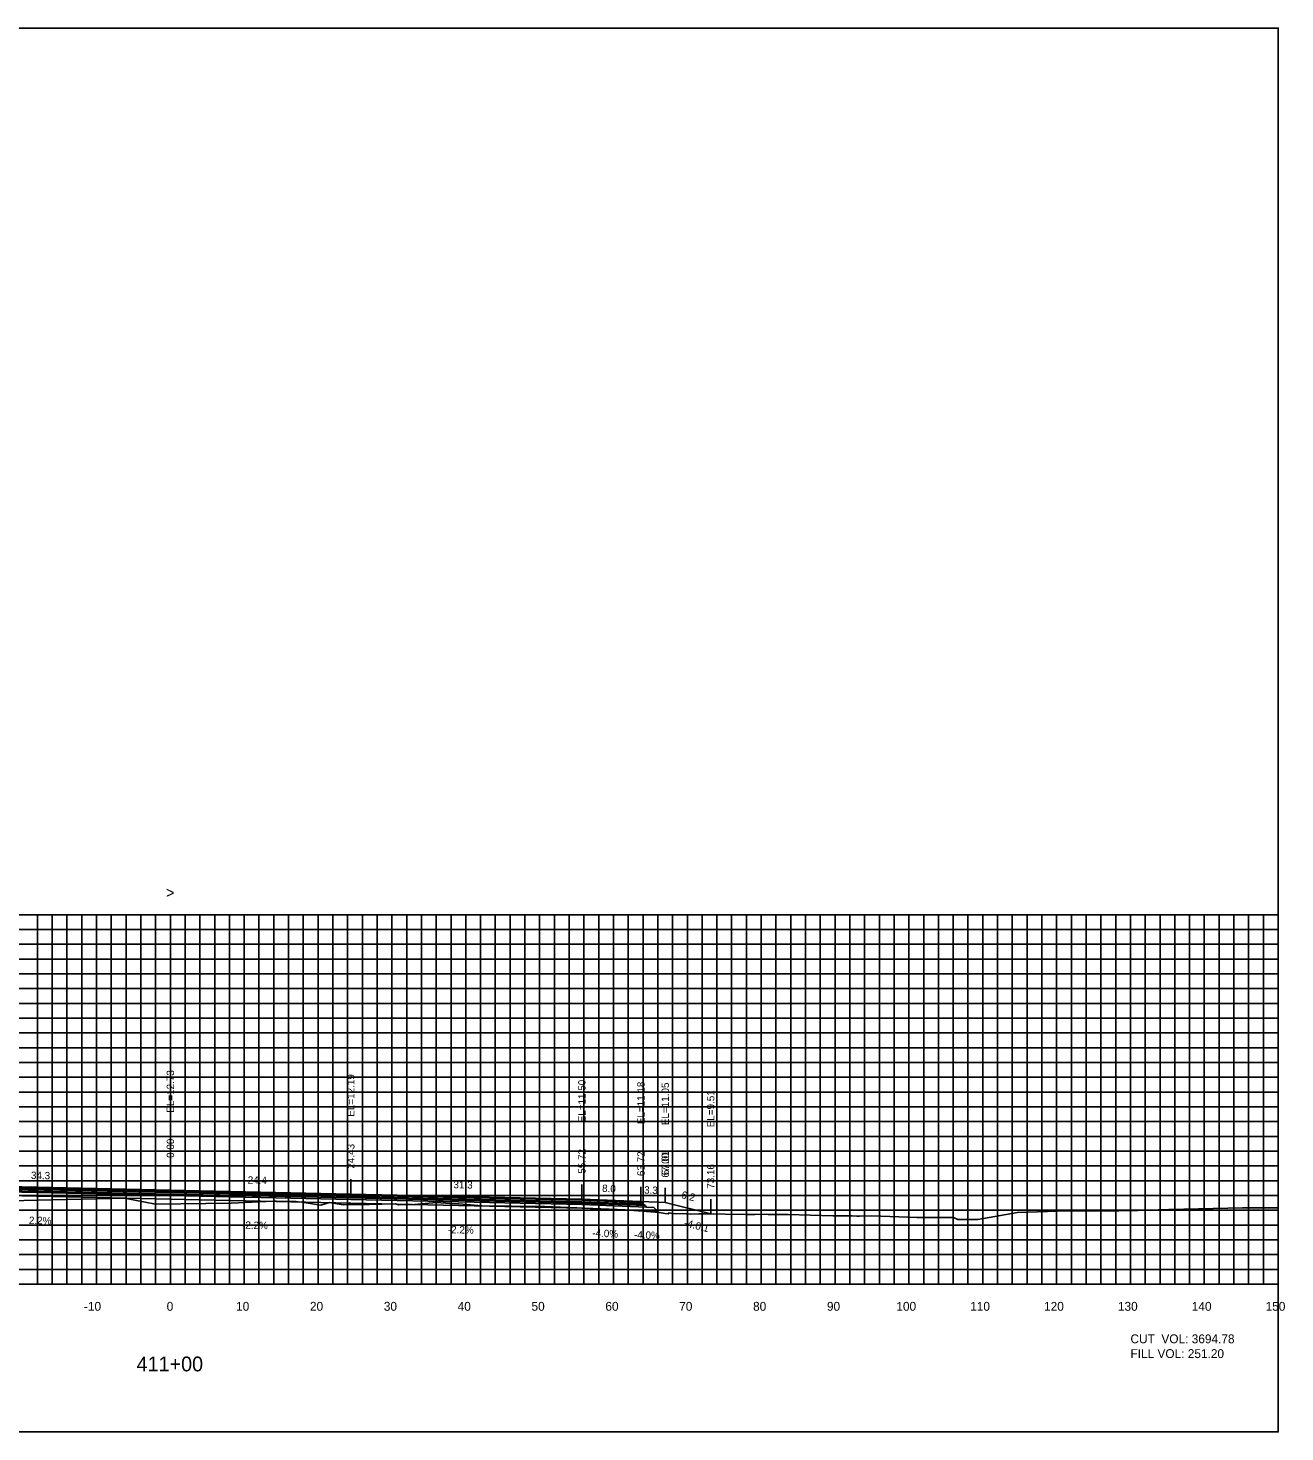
# Model space of a CAD drawing. Extents: x 1800976 to 1805104, y 250057 to 250580.
# Drawn here: x 1804651.7 to 1804821.9, y 250079.4 to 250269.4 of the extents above; entities that cross this region are included whole.
import ezdxf

# ---------------------------------------------------------------- set-up
doc = ezdxf.new("R2010")
doc.units = 0
for name, color, linetype in [('1', 7, 'Continuous'), ('10', 7, 'Continuous'), ('3', 7, 'Continuous'), ('4', 7, 'Continuous'), ('60', 7, 'Continuous'), ('ANNO-TXT', 7, 'Continuous'), ('BASE', 7, 'Continuous'), ('CL-CNST', 7, 'Continuous'), ('Level 62', 7, 'Continuous'), ('LOWER BINDER', 7, 'Continuous'), ('M-ROADS', 7, 'Continuous'), ('UPPER BINDER', 7, 'Continuous'), ('WEARING', 7, 'Continuous')]:
    doc.layers.add(name, color=color, linetype=linetype)

msp = doc.modelspace()

# ---------------------------------------------------------------- linework, layer by layer
for p, q in [((1804671, 250112.16), (1804671, 250114.16)), ((1804695.43, 250111.62), (1804695.43, 250113.62)), ((1804695.43, 250111.62), (1804695.43, 250113.62)), ((1804726.72, 250110.93), (1804726.72, 250112.93)), ((1804734.72, 250110.61), (1804734.72, 250112.61)), ((1804738.01, 250110.48), (1804738.01, 250112.48)), ((1804738.01, 250110.48), (1804738.01, 250112.48)), ((1804744.16, 250108.94), (1804744.16, 250110.94))]:
    msp.add_line(p, q)
msp.add_lwpolyline([(1804521, 250079.43), (1804821, 250079.43), (1804821, 250269.43), (1804521, 250269.43)], close=True)
at = {"layer": '60'}
for p, q in [((1804821, 250099.43), (1804821, 250149.43)), ((1804821.06, 250149.43), (1804821, 250149.43)), ((1804821.06, 250139.43), (1804821, 250139.43)), ((1804821.06, 250129.43), (1804821, 250129.43)), ((1804821.06, 250119.43), (1804821, 250119.43)), ((1804821.06, 250109.43), (1804821, 250109.43)), ((1804521, 250099.43), (1804821, 250099.43)), ((1804661, 250099.37), (1804661, 250099.43)), ((1804671, 250099.37), (1804671, 250099.43)), ((1804681, 250099.37), (1804681, 250099.43)), ((1804691, 250099.37), (1804691, 250099.43)), ((1804701, 250099.37), (1804701, 250099.43)), ((1804711, 250099.37), (1804711, 250099.43)), ((1804721, 250099.37), (1804721, 250099.43)), ((1804731, 250099.37), (1804731, 250099.43)), ((1804741, 250099.37), (1804741, 250099.43)), ((1804751, 250099.37), (1804751, 250099.43)), ((1804761, 250099.37), (1804761, 250099.43)), ((1804771, 250099.37), (1804771, 250099.43)), ((1804781, 250099.37), (1804781, 250099.43)), ((1804791, 250099.37), (1804791, 250099.43)), ((1804801, 250099.37), (1804801, 250099.43)), ((1804811, 250099.37), (1804811, 250099.43)), ((1804821, 250099.37), (1804821, 250099.43)), ((1804821.06, 250099.43), (1804821, 250099.43))]:
    msp.add_line(p, q, dxfattribs=at)
at = {"layer": 'BASE'}
msp.add_lwpolyline([(1804584.14, 250112.99), (1804585.14, 250113.03), (1804589.89, 250113.22), (1804636.73, 250112.2), (1804671, 250111.44), (1804695.43, 250110.91), (1804726.72, 250110.21), (1804735.47, 250109.86), (1804736.47, 250109.82), (1804736.99, 250109.3), (1804726.72, 250109.71), (1804695.43, 250110.41), (1804671, 250110.94), (1804636.73, 250111.7), (1804589.89, 250112.72), (1804583.62, 250112.47)], close=True, dxfattribs=at)
at = {"layer": 'CL-CNST'}
msp.add_lwpolyline([(1804554.98, 250110.17), (1804555.39, 250110.06), (1804559.39, 250110.06), (1804580.39, 250113.56), (1804585.89, 250113.78), (1804589.89, 250113.94), (1804636.72, 250112.91), (1804671, 250112.16), (1804695.43, 250111.62), (1804695.43, 250111.62), (1804726.72, 250110.93), (1804734.72, 250110.61), (1804738.01, 250110.48), (1804738.01, 250110.48), (1804744.16, 250108.94)], dxfattribs=at)
at = {"layer": 'Level 62'}
for p, q in [((1804521, 250149.43), (1804821, 250149.43)), ((1804653, 250099.43), (1804653, 250149.43)), ((1804655, 250099.43), (1804655, 250149.43)), ((1804657, 250099.43), (1804657, 250149.43)), ((1804659, 250099.43), (1804659, 250149.43)), ((1804661, 250099.43), (1804661, 250149.43)), ((1804663, 250099.43), (1804663, 250149.43)), ((1804665, 250099.43), (1804665, 250149.43)), ((1804667, 250099.43), (1804667, 250149.43)), ((1804669, 250099.43), (1804669, 250149.43)), ((1804671, 250099.43), (1804671, 250149.43)), ((1804673, 250099.43), (1804673, 250149.43)), ((1804675, 250099.43), (1804675, 250149.43)), ((1804677, 250099.43), (1804677, 250149.43)), ((1804679, 250099.43), (1804679, 250149.43)), ((1804681, 250099.43), (1804681, 250149.43)), ((1804683, 250099.43), (1804683, 250149.43)), ((1804685, 250099.43), (1804685, 250149.43)), ((1804687, 250099.43), (1804687, 250149.43)), ((1804689, 250099.43), (1804689, 250149.43)), ((1804691, 250099.43), (1804691, 250149.43)), ((1804693, 250099.43), (1804693, 250149.43)), ((1804695, 250099.43), (1804695, 250149.43)), ((1804697, 250099.43), (1804697, 250149.43)), ((1804699, 250099.43), (1804699, 250149.43)), ((1804701, 250099.43), (1804701, 250149.43)), ((1804703, 250099.43), (1804703, 250149.43)), ((1804705, 250099.43), (1804705, 250149.43)), ((1804707, 250099.43), (1804707, 250149.43)), ((1804709, 250099.43), (1804709, 250149.43)), ((1804711, 250099.43), (1804711, 250149.43)), ((1804713, 250099.43), (1804713, 250149.43)), ((1804715, 250099.43), (1804715, 250149.43)), ((1804717, 250099.43), (1804717, 250149.43)), ((1804719, 250099.43), (1804719, 250149.43)), ((1804721, 250099.43), (1804721, 250149.43)), ((1804723, 250099.43), (1804723, 250149.43)), ((1804725, 250099.43), (1804725, 250149.43)), ((1804727, 250099.43), (1804727, 250149.43)), ((1804729, 250099.43), (1804729, 250149.43)), ((1804731, 250099.43), (1804731, 250149.43)), ((1804733, 250099.43), (1804733, 250149.43)), ((1804735, 250099.43), (1804735, 250149.43)), ((1804737, 250099.43), (1804737, 250149.43)), ((1804739, 250099.43), (1804739, 250149.43)), ((1804741, 250099.43), (1804741, 250149.43)), ((1804743, 250099.43), (1804743, 250149.43)), ((1804745, 250099.43), (1804745, 250149.43)), ((1804747, 250099.43), (1804747, 250149.43)), ((1804749, 250099.43), (1804749, 250149.43)), ((1804751, 250099.43), (1804751, 250149.43)), ((1804753, 250099.43), (1804753, 250149.43)), ((1804755, 250099.43), (1804755, 250149.43)), ((1804757, 250099.43), (1804757, 250149.43)), ((1804759, 250099.43), (1804759, 250149.43)), ((1804761, 250099.43), (1804761, 250149.43)), ((1804763, 250099.43), (1804763, 250149.43)), ((1804765, 250099.43), (1804765, 250149.43)), ((1804767, 250099.43), (1804767, 250149.43)), ((1804769, 250099.43), (1804769, 250149.43)), ((1804771, 250099.43), (1804771, 250149.43)), ((1804773, 250099.43), (1804773, 250149.43)), ((1804775, 250099.43), (1804775, 250149.43)), ((1804777, 250099.43), (1804777, 250149.43)), ((1804779, 250099.43), (1804779, 250149.43)), ((1804781, 250099.43), (1804781, 250149.43)), ((1804783, 250099.43), (1804783, 250149.43)), ((1804785, 250099.43), (1804785, 250149.43)), ((1804787, 250099.43), (1804787, 250149.43)), ((1804789, 250099.43), (1804789, 250149.43)), ((1804791, 250099.43), (1804791, 250149.43)), ((1804793, 250099.43), (1804793, 250149.43)), ((1804795, 250099.43), (1804795, 250149.43)), ((1804797, 250099.43), (1804797, 250149.43)), ((1804799, 250099.43), (1804799, 250149.43)), ((1804801, 250099.43), (1804801, 250149.43)), ((1804803, 250099.43), (1804803, 250149.43)), ((1804805, 250099.43), (1804805, 250149.43)), ((1804807, 250099.43), (1804807, 250149.43)), ((1804809, 250099.43), (1804809, 250149.43)), ((1804811, 250099.43), (1804811, 250149.43)), ((1804813, 250099.43), (1804813, 250149.43)), ((1804815, 250099.43), (1804815, 250149.43)), ((1804817, 250099.43), (1804817, 250149.43)), ((1804819, 250099.43), (1804819, 250149.43)), ((1804821, 250099.43), (1804821, 250149.43)), ((1804521, 250147.43), (1804821, 250147.43)), ((1804521, 250145.43), (1804821, 250145.43)), ((1804521, 250143.43), (1804821, 250143.43)), ((1804521, 250141.43), (1804821, 250141.43)), ((1804521, 250139.43), (1804821, 250139.43)), ((1804521, 250137.43), (1804821, 250137.43)), ((1804521, 250135.43), (1804821, 250135.43)), ((1804521, 250133.43), (1804821, 250133.43)), ((1804521, 250131.43), (1804821, 250131.43)), ((1804521, 250129.43), (1804821, 250129.43)), ((1804521, 250127.43), (1804821, 250127.43)), ((1804521, 250125.43), (1804821, 250125.43)), ((1804521, 250123.43), (1804821, 250123.43)), ((1804521, 250121.43), (1804821, 250121.43)), ((1804521, 250119.43), (1804821, 250119.43)), ((1804521, 250117.43), (1804821, 250117.43)), ((1804521, 250115.43), (1804821, 250115.43)), ((1804521, 250113.43), (1804821, 250113.43)), ((1804521, 250111.43), (1804821, 250111.43)), ((1804521, 250109.43), (1804821, 250109.43)), ((1804521, 250107.43), (1804821, 250107.43)), ((1804521, 250105.43), (1804821, 250105.43)), ((1804521, 250103.43), (1804821, 250103.43)), ((1804521, 250101.43), (1804821, 250101.43)), ((1804521, 250099.43), (1804821, 250099.43))]:
    msp.add_line(p, q, dxfattribs=at)
at = {"layer": 'LOWER BINDER'}
for points in [[(1804589.89, 250113.41), (1804636.72, 250112.38), (1804671, 250111.63), (1804695.43, 250111.1), (1804726.72, 250110.4), (1804735.27, 250110.06), (1804735.47, 250109.86), (1804726.72, 250110.21), (1804695.43, 250110.91), (1804671, 250111.44), (1804636.73, 250112.2), (1804589.89, 250113.22), (1804585.14, 250113.03), (1804585.34, 250113.23)], [(1804589.89, 250113.6), (1804636.72, 250112.57), (1804671, 250111.82), (1804695.43, 250111.28), (1804726.72, 250110.59), (1804735.08, 250110.26), (1804735.27, 250110.06), (1804726.72, 250110.4), (1804695.43, 250111.1), (1804671, 250111.63), (1804636.72, 250112.38), (1804589.89, 250113.41), (1804585.34, 250113.23), (1804585.53, 250113.43)]]:
    msp.add_lwpolyline(points, close=True, dxfattribs=at)
at = {"layer": 'M-ROADS'}
msp.add_lwpolyline([(1804641.38, 250110.51), (1804664.81, 250111.06), (1804668.97, 250110.26), (1804679.24, 250110.37), (1804684.91, 250110.66), (1804685.33, 250110.67), (1804688.04, 250110.63), (1804688.29, 250110.59), (1804688.79, 250110.55), (1804691.38, 250110.12), (1804692.54, 250110.48), (1804694.4, 250110.15), (1804695.12, 250110.19), (1804697.91, 250110.21), (1804701.44, 250110.28), (1804701.94, 250110.17), (1804704.06, 250110.23), (1804707.05, 250110.47), (1804708.85, 250110.36), (1804710.04, 250110.29), (1804713.16, 250110.05), (1804721.25, 250109.95), (1804721.65, 250109.92), (1804722.72, 250109.91), (1804732.57, 250109.51), (1804737.24, 250109.11), (1804737.97, 250109.01), (1804738.42, 250108.94), (1804738.48, 250109.07), (1804739.36, 250108.96), (1804740.37, 250108.98), (1804740.83, 250108.95), (1804740.9, 250108.95), (1804741.36, 250108.91), (1804742.57, 250108.94), (1804743.32, 250108.95), (1804748.96, 250108.87), (1804749.76, 250108.85), (1804750.14, 250108.86), (1804751.68, 250108.89), (1804751.94, 250108.87), (1804752.48, 250108.86), (1804752.65, 250108.86), (1804752.73, 250108.85), (1804753.22, 250108.86), (1804754.65, 250108.87), (1804760.72, 250108.67), (1804761.09, 250108.66), (1804761.18, 250108.66), (1804762.96, 250108.68), (1804763.31, 250108.67), (1804763.97, 250108.65), (1804764.05, 250108.64), (1804764.09, 250108.64), (1804764.32, 250108.65), (1804765.96, 250108.67), (1804769.62, 250108.54), (1804772.06, 250108.46), (1804773.81, 250108.47), (1804774.07, 250108.47), (1804774.1, 250108.47), (1804774.21, 250108.46), (1804774.81, 250108.44), (1804775, 250108.43), (1804776.51, 250108.45), (1804776.98, 250108.46), (1804777.02, 250108.43), (1804777.61, 250108.16), (1804779.43, 250108.16), (1804779.83, 250108.2), (1804780.35, 250108.19), (1804785.7, 250109.14), (1804791.11, 250109.33), (1804793.67, 250109.36), (1804795.79, 250109.37), (1804799.41, 250109.37), (1804800.92, 250109.4), (1804801.28, 250109.4), (1804802.01, 250109.41), (1804806.21, 250109.52), (1804810.19, 250109.62), (1804816.19, 250109.77), (1804816.26, 250109.77), (1804816.37, 250109.77), (1804820.31, 250109.77), (1804821, 250109.76)], dxfattribs=at)
at = {"layer": 'UPPER BINDER'}
msp.add_lwpolyline([(1804726.72, 250110.59), (1804735.08, 250110.26), (1804734.88, 250110.46), (1804726.72, 250110.78), (1804695.43, 250111.47), (1804671, 250112.01), (1804636.72, 250112.76), (1804589.89, 250113.79), (1804585.73, 250113.63), (1804585.53, 250113.43), (1804589.89, 250113.6), (1804636.72, 250112.57), (1804671, 250111.82), (1804695.43, 250111.28)], close=True, dxfattribs=at)
at = {"layer": 'WEARING'}
msp.add_lwpolyline([(1804726.72, 250110.78), (1804734.88, 250110.46), (1804734.72, 250110.61), (1804726.72, 250110.93), (1804695.43, 250111.62), (1804671, 250112.16), (1804636.72, 250112.91), (1804589.89, 250113.94), (1804585.89, 250113.78), (1804585.73, 250113.63), (1804589.89, 250113.79), (1804636.72, 250112.76), (1804671, 250112.01), (1804695.43, 250111.47)], close=True, dxfattribs=at)

# ---------------------------------------------------------------- texts
msp.add_text('-4.0:1', height=1, rotation=345.9638).set_placement((1804740.48, 250107.29))
at = {"layer": '1'}
msp.add_text('411+00', height=2, dxfattribs=at).set_placement((1804666.43, 250087.63))
at = {"layer": '10'}
for s, p in [('-10', (1804659.3, 250095.83)), ('0', (1804670.5, 250095.83)), ('10', (1804679.9, 250095.83)), ('20', (1804689.9, 250095.83)), ('30', (1804699.9, 250095.83)), ('40', (1804709.9, 250095.83)), ('50', (1804719.9, 250095.83)), ('60', (1804729.9, 250095.83)), ('70', (1804739.9, 250095.83)), ('80', (1804749.9, 250095.83)), ('90', (1804759.9, 250095.83)), ('100', (1804769.3, 250095.83)), ('110', (1804779.3, 250095.83)), ('120', (1804789.3, 250095.83)), ('130', (1804799.3, 250095.83)), ('140', (1804809.3, 250095.83)), ('150', (1804819.3, 250095.83))]:
    msp.add_text(s, height=1.2, dxfattribs=at).set_placement(p)
at = {"layer": '3'}
for s, p in [('EL=12.73', (1804671.5, 250122.63)), ('EL=12.19', (1804695.93, 250122.09)), ('EL=12.19', (1804695.93, 250122.09)), ('EL=11.50', (1804727.22, 250121.33)), ('EL=11.18', (1804735.22, 250121.08)), ('EL=11.05', (1804738.51, 250120.95)), ('EL=11.05', (1804738.51, 250120.95)), ('EL=9.51', (1804744.66, 250120.66)), ('0.00', (1804671.5, 250116.52)), ('24.43', (1804695.93, 250115.07)), ('24.43', (1804695.93, 250115.07)), ('55.72', (1804727.22, 250114.38)), ('63.72', (1804735.22, 250114.06)), ('67.01', (1804738.51, 250114.18)), ('67.00', (1804738.51, 250113.85)), ('73.16', (1804744.66, 250112.34))]:
    msp.add_text(s, height=1, rotation=90, dxfattribs=at).set_placement(p)
at = {"layer": '4'}
for s, rotation, p in [('34.3', 358.7397, (1804652.11, 250113.67)), ('24.4', 358.7397, (1804681.46, 250113.03)), ('31.3', 358.7397, (1804709.32, 250112.42)), ('8.0', 357.7094, (1804729.44, 250111.92)), ('3.3', 357.7094, (1804735.13, 250111.7)), ('6.2', 345.9638, (1804740.11, 250111.09)), ('2.2%', 358.7397, (1804651.84, 250107.58)), ('-2.2%', 358.7397, (1804680.7, 250106.94)), ('-2.2%', 358.7397, (1804708.56, 250106.33)), ('-4.0%', 357.7094, (1804728.11, 250105.87)), ('-4.0%', 357.7094, (1804733.76, 250105.65))]:
    msp.add_text(s, height=1, rotation=rotation, dxfattribs=at).set_placement(p)
at = {"layer": '60'}
msp.add_text('>', height=1.5, dxfattribs=at).set_placement((1804670.39, 250151.68))
at = {"layer": 'ANNO-TXT'}
for s, p in [('CUT  VOL: 3694.78', (1804801, 250091.43)), ('FILL VOL: 251.20', (1804801, 250089.43))]:
    msp.add_text(s, height=1.2, dxfattribs=at).set_placement(p)

doc.saveas('drawing.dxf')
